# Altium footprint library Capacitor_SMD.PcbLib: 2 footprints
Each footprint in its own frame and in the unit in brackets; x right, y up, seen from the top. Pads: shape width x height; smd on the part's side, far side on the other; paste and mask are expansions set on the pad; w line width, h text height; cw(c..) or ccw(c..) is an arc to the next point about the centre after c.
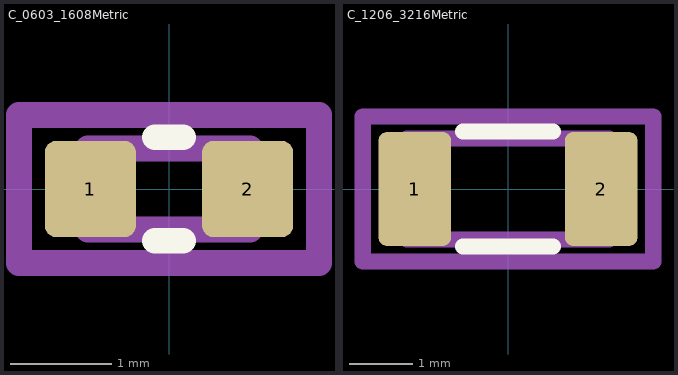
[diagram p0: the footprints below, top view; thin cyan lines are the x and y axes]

## C_0603_1608Metric [mm]
pads (2):
  rrect25% 0.9x0.95 smd: 1(-0.775,0) 2(0.775,0)
F.SilkS:
  lines w0.254: -0.141,-0.51 0.141,-0.51 ; -0.141,0.51 0.141,0.51
F.CrtYd:
  lines w0.254: -1.48,-0.73 -1.48,0.73 1.48,0.73 1.48,-0.73 -1.48,-0.73
F.Fab:
  lines w0.254: -0.8,-0.4 -0.8,0.4 0.8,0.4 0.8,-0.4 -0.8,-0.4
  text "'.Designator'" at -1.619,-0.336 h0.4

## C_1206_3216Metric [mm]
pads (2):
  rrect22% 1.15x1.8 smd: 1(-1.475,0) 2(1.475,0)
F.SilkS:
  lines w0.254: -0.711,-0.91 0.711,-0.91 ; -0.711,0.91 0.711,0.91
F.CrtYd:
  lines w0.254: -2.3,-1.15 -2.3,1.15 2.3,1.15 2.3,-1.15 -2.3,-1.15
F.Fab:
  lines w0.254: -1.6,-0.8 -1.6,0.8 1.6,0.8 1.6,-0.8 -1.6,-0.8
  text "'.Designator'" at -3.237,-0.672 h0.8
